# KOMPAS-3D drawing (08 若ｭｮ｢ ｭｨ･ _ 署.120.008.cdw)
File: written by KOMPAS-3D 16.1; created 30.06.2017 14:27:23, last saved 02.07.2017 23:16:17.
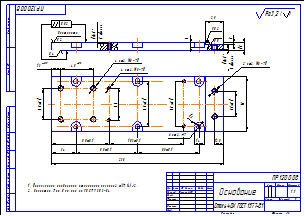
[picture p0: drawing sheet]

Sheet 1: A3, landscape

Title block, sheet 1: name: Основание; designation: ПР.120.008; material: Сталь 40Х ГОСТ 1577-81; scale: 1:1; sheets: 1; sheet format: A3; stored path: C:\Users\2\Desktop\SIS70\Прохвост\Основание _ К17.479.008.cdw; drawn by: Сигачев СИ

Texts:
  Сигачев
  romans
  txt
  Притереть
  Неуказанные предельные отклонения размеров  (IT 14)/2.
  Покрытие: Хим. Окс. прм по ГОСТ 9.303-84.
  Ra3,2
  Ra3,2 ( )
Dimensions and other numbers on the sheet: 0,8; 0,4; 0,2; 0,02; 1; 8 фасок; 6; 25; 4 фаски; 2; 10; 7; 6 отв.; 44; 13; 45; 43±0,1; -7Н; 4 отв.; 5; 8; 63±0,1; 62±0,1; 2 отв.; 35±0,1; 75; 12,5; 14; 103±0,1; 80±0,1; 34; 85±0,1; 238; 1:1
